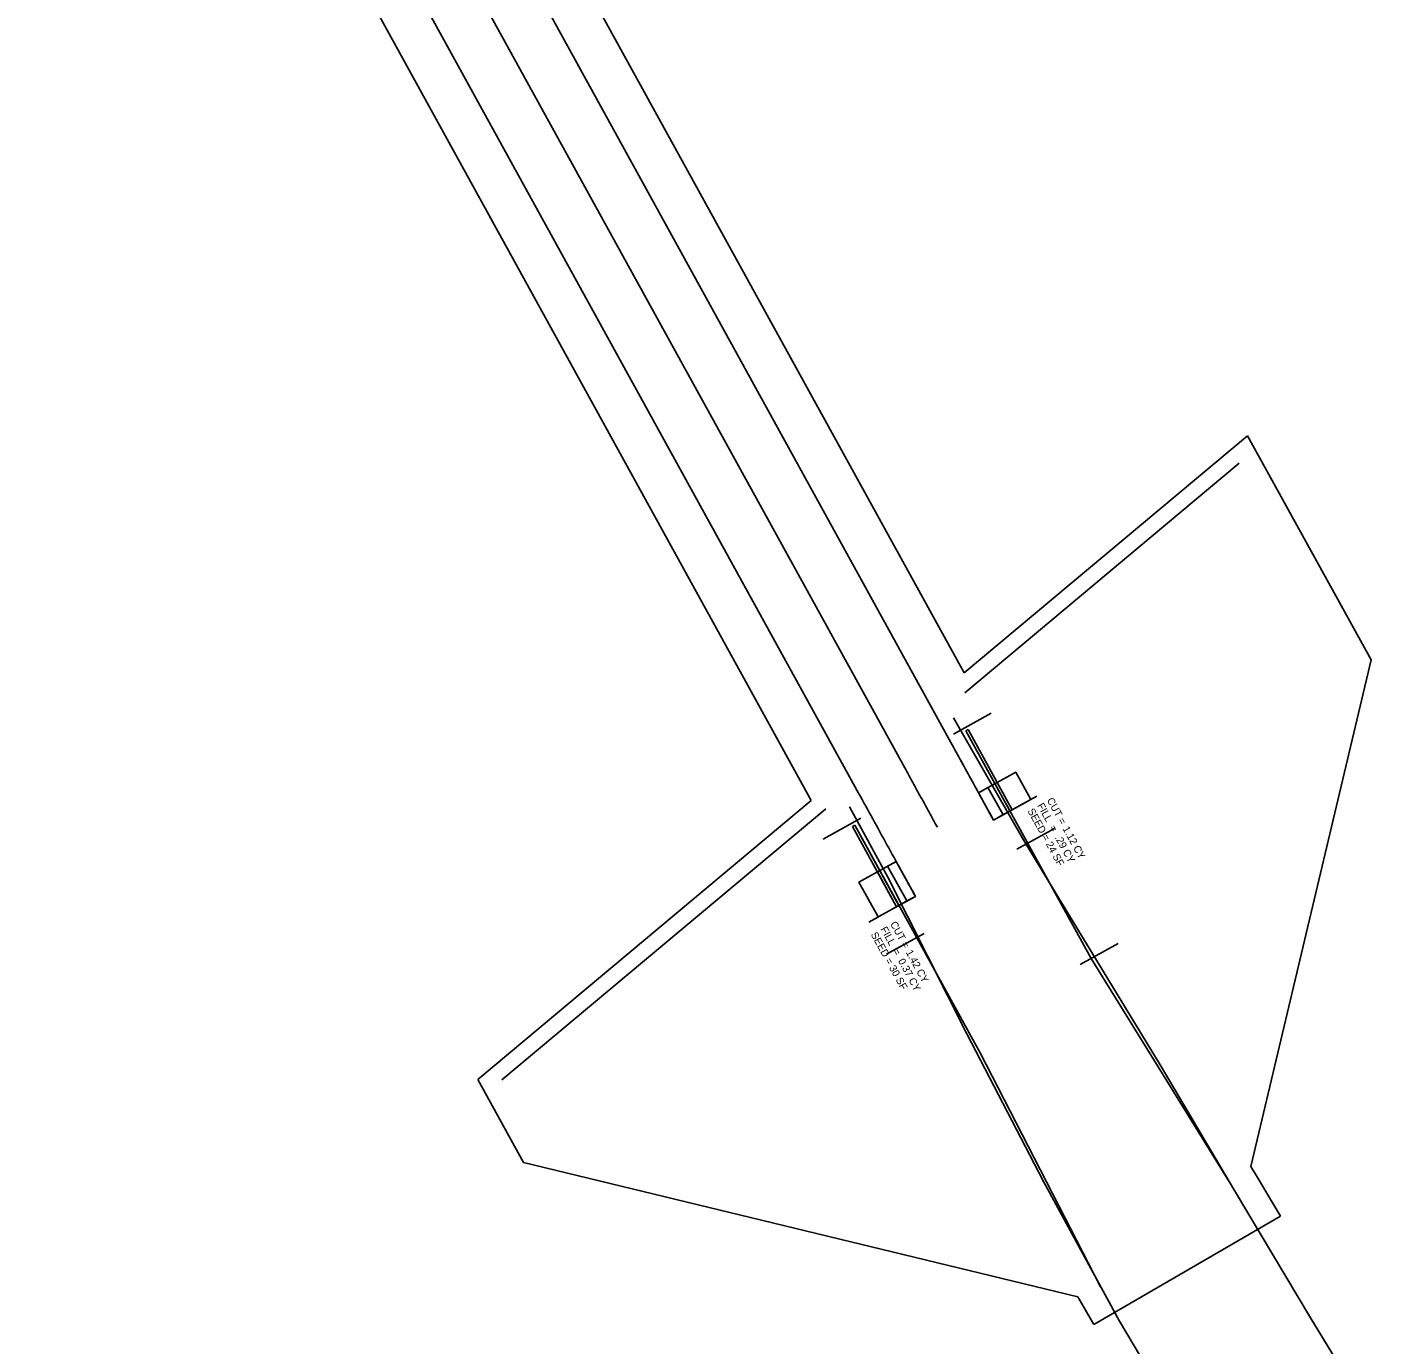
# Model space of a CAD drawing. Extents: x 1494134 to 1494615, y 514855 to 515612.
# Drawn here: x 1494204.2 to 1494463.7, y 515111 to 515361.3 of the extents above; entities that cross this region are included whole.
import ezdxf

# ---------------------------------------------------------------- set-up
doc = ezdxf.new("R2010")
doc.units = 0
for name, color, linetype in [('BR_P_Rail_Object', 7, 'Continuous'), ('BR_P_Slab_Const_Joint', 7, 'Continuous'), ('BR_P_Slab_Object', 7, 'Continuous'), ('BR_P_Sub_Object', 7, 'Continuous'), ('BR_X_Beam_Stl_Det', 7, 'Continuous'), ('BR_X_Rail_Object', 7, 'Continuous'), ('BR_X_Sub_Foot_Hidden', 7, 'Continuous'), ('Default', 7, 'Continuous'), ('PV_P_Curb', 7, 'Continuous'), ('RW_X_CL', 7, 'Continuous'), ('RW_X_Fee_WL', 7, 'Continuous'), ('SC_Scratch2', 7, 'Continuous'), ('SV_P_Control_Cells_Set', 7, 'Continuous')]:
    doc.layers.add(name, color=color, linetype=linetype)

msp = doc.modelspace()

# ---------------------------------------------------------------- linework, layer by layer
at = {"layer": 'BR_P_Rail_Object'}
for p, q in [((1494382.39, 515234.9), (1494434.54, 515278.5)), ((1494294.33, 515161.3), (1494355.94, 515212.8))]:
    msp.add_line(p, q, dxfattribs=at)
at = {"layer": 'BR_P_Slab_Const_Joint'}
for p, q in [((1494392.05, 515219.76), (1494388.55, 515217.83)), ((1494394.9, 515214.59), (1494392.05, 515219.76)), ((1494386.77, 515216.85), (1494387.88, 515214.86)), ((1494388.55, 515217.83), (1494391.4, 515212.66)), ((1494387.88, 515214.86), (1494389.63, 515211.68)), ((1494391.4, 515212.66), (1494394.9, 515214.59)), ((1494362.25, 515198.91), (1494365.76, 515200.84)), ((1494365.76, 515200.84), (1494369.4, 515194.22)), ((1494367.7, 515201.91), (1494371.38, 515195.31)), ((1494365.89, 515192.29), (1494362.25, 515198.91)), ((1494369.4, 515194.22), (1494365.89, 515192.29))]:
    msp.add_line(p, q, dxfattribs=at)
for points in [[(1494388.55, 515217.83), (1494392.05, 515219.76), (1494394.9, 515214.59), (1494391.4, 515212.66)], [(1494388.55, 515217.83), (1494391.4, 515212.66), (1494387.83, 515210.69), (1494384.98, 515215.87)], [(1494369.4, 515194.22), (1494365.89, 515192.29), (1494362.25, 515198.91), (1494365.76, 515200.84)], [(1494369.33, 515202.81), (1494372.98, 515196.19), (1494369.4, 515194.22), (1494365.75, 515200.84)]]:
    msp.add_lwpolyline(points, close=True, dxfattribs=at)
for points in [[(1494384.97, 515215.86), (1494386.77, 515216.85), (1494387.88, 515214.86), (1494389.63, 515211.68), (1494387.83, 515210.69)], [(1494372.98, 515196.19), (1494371.38, 515195.31), (1494367.7, 515201.91), (1494369.28, 515202.77), (1494369.33, 515202.81)]]:
    msp.add_lwpolyline(points, dxfattribs=at)
for points in [[(1494387.83, 515210.69), (1494387.59, 515211.12), (1494387.11, 515211.98), (1494386.4, 515213.28), (1494385.69, 515214.57), (1494385.21, 515215.43), (1494384.97, 515215.86)], [(1494369.33, 515202.81), (1494369.64, 515202.26), (1494370.25, 515201.15), (1494371.16, 515199.5), (1494372.07, 515197.85), (1494372.68, 515196.74), (1494372.98, 515196.19)]]:
    msp.add_open_spline(points, degree=3, dxfattribs=at)
at = {"layer": 'BR_P_Slab_Object'}
for p, q in [((1494219.01, 515517.37), (1494379.7, 515225.45)), ((1494204.16, 515502.87), (1494362.18, 515215.81))]:
    msp.add_line(p, q, dxfattribs=at)
for points in [[(1494379.7, 515225.45), (1494381.05, 515222.99), (1494383.76, 515218.07), (1494386.47, 515213.15), (1494387.83, 515210.69)], [(1494362.18, 515215.81), (1494363.98, 515212.54), (1494367.57, 515206), (1494371.18, 515199.46), (1494372.98, 515196.19)]]:
    msp.add_open_spline(points, degree=3, dxfattribs=at)
at = {"layer": 'BR_P_Sub_Object'}
msp.add_line((1494214.83, 515504.21), (1494370.94, 515220.63), dxfattribs=at)
msp.add_open_spline([(1494370.94, 515220.63), (1494371.45, 515219.69), (1494372.49, 515217.81), (1494374.04, 515214.99), (1494375.59, 515212.17), (1494376.63, 515210.29), (1494377.15, 515209.35)], degree=3, dxfattribs=at)
at = {"layer": 'BR_X_Beam_Stl_Det'}
for points in [[(1494380.2, 515230.1), (1494393.6, 515206.82), (1494404.91, 515188.1), (1494419.49, 515164.2), (1494433.64, 515140.28), (1494448.07, 515116.06), (1494463.58, 515090.64), (1494479.58, 515065.68), (1494496.77, 515040.94), (1494511.81, 515019.84), (1494528.7, 514997.55), (1494534.82, 514990.5), (1494539.21, 514986.72), (1494545.71, 514983.58), (1494551.03, 514982.11), (1494556.35, 514982.04), (1494561.72, 514982.95), (1494569.19, 514985.24), (1494576.63, 514988.93)], [(1494614.91, 514854.87), (1494597.09, 514872.4), (1494580.35, 514889.21), (1494562.88, 514908.05), (1494550.1, 514922.29), (1494533.87, 514941.34), (1494520.35, 514956.01), (1494505.9, 514974.85), (1494487.53, 514999.55), (1494471.53, 515021.85), (1494455.58, 515044.88), (1494439.7, 515069.37), (1494424.95, 515093.26), (1494411.75, 515115.45), (1494397.32, 515142.01), (1494382.74, 515170.08), (1494367.73, 515199.81), (1494360.42, 515213.23)]]:
    msp.add_lwpolyline(points, dxfattribs=at)
at = {"layer": 'BR_X_Rail_Object'}
for p, q in [((1494238.61, 515499.56), (1494382.22, 515238.67)), ((1494353.16, 515214.38), (1494209.58, 515475.23)), ((1494382.22, 515238.67), (1494436.13, 515283.74)), ((1494436.13, 515283.74), (1494459.6, 515241.16)), ((1494459.6, 515241.16), (1494436.77, 515144.87)), ((1494289.78, 515161.41), (1494353.16, 515214.38)), ((1494298.49, 515145.63), (1494289.78, 515161.41)), ((1494298.49, 515145.63), (1494403.83, 515120.1)), ((1494442.39, 515135.4), (1494406.89, 515114.82)), ((1494403.83, 515120.1), (1494406.89, 515114.82))]:
    msp.add_line(p, q, dxfattribs=at)
msp.add_lwpolyline([(1494442.39, 515135.4), (1494438.01, 515142.78), (1494436.77, 515144.87)], dxfattribs=at)
at = {"layer": 'BR_X_Sub_Foot_Hidden'}
for points in [[(1494384.97, 515215.86), (1494385.21, 515215.43), (1494385.69, 515214.57), (1494386.4, 515213.28), (1494387.11, 515211.98), (1494387.59, 515211.12), (1494387.83, 515210.69)], [(1494369.33, 515202.81), (1494369.64, 515202.26), (1494370.25, 515201.15), (1494371.16, 515199.5), (1494372.07, 515197.85), (1494372.68, 515196.74), (1494372.98, 515196.19)]]:
    msp.add_open_spline(points, degree=3, dxfattribs=at)
at = {"layer": 'Default'}
msp.add_line((1494369.33, 515202.81), (1494369.28, 515202.77), dxfattribs=at)
at = {"layer": 'PV_P_Curb'}
for p, q in [((1494383.01, 515227.9), (1494382.57, 515227.65)), ((1494390.96, 515212.42), (1494382.57, 515227.65)), ((1494391.4, 515212.66), (1494383.01, 515227.9)), ((1494391.4, 515212.66), (1494390.96, 515212.42)), ((1494361.45, 515209.7), (1494361.01, 515209.46)), ((1494369.4, 515194.22), (1494361.01, 515209.46)), ((1494369.83, 515194.46), (1494361.45, 515209.7)), ((1494369.83, 515194.46), (1494369.4, 515194.22))]:
    msp.add_line(p, q, dxfattribs=at)
at = {"layer": 'RW_X_CL'}
for p, q in [((1494361.45, 515209.7), (1494385.27, 515166.43)), ((1494385.27, 515166.43), (1494408.19, 515121.99))]:
    msp.add_line(p, q, dxfattribs=at)
at = {"layer": 'RW_X_Fee_WL'}
for p, q in [((1494390.96, 515212.42), (1494387.83, 515210.69)), ((1494372.98, 515196.19), (1494369.83, 515194.46))]:
    msp.add_line(p, q, dxfattribs=at)
at = {"layer": 'SC_Scratch2'}
for p, q in [((1494387.39, 515231), (1494380.21, 515227.04)), ((1494396.07, 515215.23), (1494388.89, 515211.28)), ((1494362.61, 515211.03), (1494355.44, 515207.08)), ((1494399.45, 515209.1), (1494392.27, 515205.14)), ((1494371.3, 515195.26), (1494364.12, 515191.31)), ((1494374.67, 515189.13), (1494367.49, 515185.18)), ((1494411.5, 515187.2), (1494404.32, 515183.24))]:
    msp.add_line(p, q, dxfattribs=at)
at = {"layer": 'SV_P_Control_Cells_Set'}
for p, q in [((1494382.57, 515227.65), (1494406.39, 515184.38)), ((1494406.39, 515184.38), (1494432.71, 515141.87))]:
    msp.add_line(p, q, dxfattribs=at)

# ---------------------------------------------------------------- texts
at = {"layer": 'BR_P_Slab_Const_Joint'}
for s, p in [('FILL  =  .29 CY', (1494396.08, 515213.46)), ('CUT =', (1494397.91, 515214.48)), ('SEED = 24 SF', (1494394.24, 515212.45)), (' 1.12 CY', (1494400.65, 515209.51)), ('FILL  =  0.37 CY', (1494366.28, 515189.97)), ('CUT =', (1494368.12, 515190.98)), ('SEED = 30 SF', (1494364.44, 515188.95)), (' 1.42 CY', (1494370.85, 515186.01))]:
    msp.add_text(s, height=1.4, rotation=298.8312, dxfattribs=at).set_placement(p)

doc.saveas('drawing.dxf')
